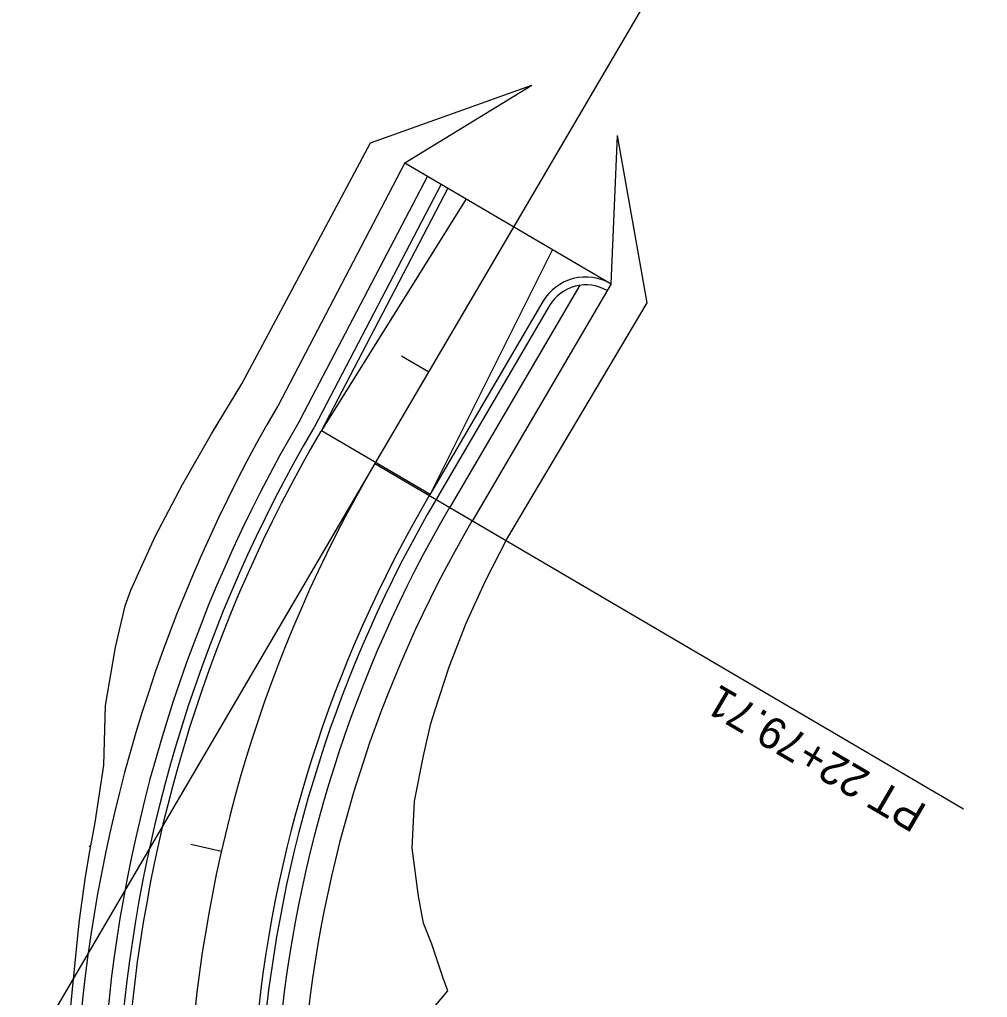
# Model space of a CAD drawing. Extents: x 979959 to 994833, y 1835619 to 1845316.
# Drawn here: x 981656.2 to 981840.6, y 1841929.5 to 1842115.7 of the extents above; entities that cross this region are included whole.
import ezdxf

# ---------------------------------------------------------------- set-up
doc = ezdxf.new("R2010")
doc.units = 0
for name, color, linetype in [('R_Horz Alg', 7, 'Continuous'), ('R_Horz Alg Annot', 7, 'Continuous'), ('R_Horz Alg Annot_Side Road', 7, 'Continuous'), ('R_Horz Alg Stationing', 7, 'Continuous'), ('R_OBLI_EXIST', 7, 'Continuous'), ('R_Proposed Const Limits', 7, 'Continuous'), ('R_Proposed Road', 7, 'Continuous')]:
    doc.layers.add(name, color=color, linetype=linetype)

msp = doc.modelspace()

# ---------------------------------------------------------------- linework, layer by layer
at = {"layer": 'R_Horz Alg'}
msp.add_line((981840.56, 1842230.25), (981723.87, 1842031.17), dxfattribs=at)
msp.add_arc((981948.55, 1841899.47), 260.44, 149.6236, 203.3367, dxfattribs=at)
at = {"layer": 'R_Horz Alg Annot'}
msp.add_lwpolyline([(981723.87, 1842031.17), (981836.02, 1841965.43)], dxfattribs=at)
at = {"layer": 'R_Horz Alg Annot_Side Road'}
msp.add_line((981723.87, 1842031.17), (981657.18, 1841917.39), dxfattribs=at)
at = {"layer": 'R_Horz Alg Stationing'}
for points in [[(981728.95, 1842051.7), (981734.13, 1842048.67)], [(981688.78, 1841958.68), (981694.63, 1841957.34)]]:
    msp.add_lwpolyline(points, dxfattribs=at)
at = {"layer": 'R_OBLI_EXIST'}
msp.add_line((981669.7, 1841958.14), (981669.41, 1841958.31), dxfattribs=at)
at = {"layer": 'R_Proposed Const Limits'}
for points in [[(981656.17, 1841869.69), (981657.38, 1841875.22), (981660.1, 1841886.57), (981662.43, 1841897.67), (981664.4, 1841908.6), (981665.12, 1841919.49), (981666.19, 1841930.34), (981667.26, 1841941.21), (981667.6, 1841944.19), (981668.67, 1841952.05), (981669.43, 1841956.68), (981670.58, 1841962.83), (981672.23, 1841973.71), (981672.57, 1841985.11), (981674.46, 1841996.2), (981676.3, 1842004.05), (981677.34, 1842007.06), (981681.99, 1842017.26), (981687.21, 1842027.16), (981692.75, 1842036.86), (981698.53, 1842046.35), (981723.05, 1842092.25), (981753.75, 1842103.23)], [(981788.82, 1841887.9), (981764.99, 1841891.26), (981744.94, 1841898.19), (981739.4, 1841906.19), (981733.08, 1841914.69), (981731.41, 1841923.21), (981737.74, 1841930.75), (981736.84, 1841933.17), (981734.7, 1841939.64), (981733.12, 1841943.63), (981732.17, 1841948.79), (981730.95, 1841957.94), (981731.42, 1841966.85), (981733.12, 1841975.5), (981734.55, 1841981.67), (981735.25, 1841984.09), (981738.03, 1841992.49), (981741.22, 1842000.77), (981744.93, 1842008.83), (981748.97, 1842016.79), (981775.71, 1842061.76), (981770.11, 1842093.65)]]:
    msp.add_lwpolyline(points, dxfattribs=at)
at = {"layer": 'R_Proposed Road'}
for p, q in [((981729.56, 1842088.44), (981753.75, 1842103.23)), ((981768.86, 1842065.4), (981770.11, 1842093.65)), ((981729.56, 1842088.44), (981705.35, 1842042.09)), ((981729.56, 1842088.44), (981768.86, 1842065.4)), ((981733.88, 1842085.9), (981709.72, 1842039.66)), ((981736.47, 1842084.39), (981712.33, 1842038.18)), ((981737.77, 1842083.63), (981713.66, 1842037.48)), ((981741.22, 1842081.6), (981713.66, 1842037.48)), ((981757.7, 1842071.94), (981734.37, 1842025.35)), ((981762.9, 1842065.12), (981738.25, 1842023.07)), ((981768.86, 1842065.4), (981742.56, 1842020.54)), ((981755.86, 1842062.01), (981734.37, 1842025.35)), ((981757.15, 1842061.25), (981735.66, 1842024.59)), ((981705.35, 1842042.09), (981705.32, 1842042.04)), ((981709.72, 1842039.66), (981709.63, 1842039.51)), ((981712.37, 1842038.24), (981712.22, 1842037.99)), ((981713.66, 1842037.48), (981713.51, 1842037.23)), ((981713.66, 1842037.48), (981734.37, 1842025.35)), ((981734.37, 1842025.35), (981734.22, 1842025.1)), ((981735.66, 1842024.59), (981735.51, 1842024.34)), ((981738.25, 1842023.07), (981738.1, 1842022.82)), ((981742.56, 1842020.54), (981742.42, 1842020.29))]:
    msp.add_line(p, q, dxfattribs=at)
for centre, radius, start, end in [((981764.05, 1842057.21), 9.5, 59.6236, 149.6236), ((981764.05, 1842057.21), 8, 59.6236, 149.6236), ((981948.55, 1841899.47), 281.94, 149.6236, 201.2591), ((981948.55, 1841899.47), 276.94, 149.6236, 201.2591), ((981948.55, 1841899.47), 273.94, 149.6236, 201.2591), ((981948.55, 1841899.47), 272.44, 149.6236, 201.2591), ((981948.55, 1841899.47), 248.44, 149.6236, 200.4683), ((981948.55, 1841899.47), 246.94, 149.6236, 200.4683), ((981948.55, 1841899.47), 243.94, 149.6236, 200.4683), ((981948.55, 1841899.47), 238.94, 149.6236, 200.4683)]:
    msp.add_arc(centre, radius, start, end, dxfattribs=at)

# ---------------------------------------------------------------- texts
at = {"layer": 'R_Horz Alg Annot'}
msp.add_text('PT 22+79.71', height=6, rotation=149.6236, dxfattribs=at).set_placement((981829.33, 1841965.87))

doc.saveas('drawing.dxf')
